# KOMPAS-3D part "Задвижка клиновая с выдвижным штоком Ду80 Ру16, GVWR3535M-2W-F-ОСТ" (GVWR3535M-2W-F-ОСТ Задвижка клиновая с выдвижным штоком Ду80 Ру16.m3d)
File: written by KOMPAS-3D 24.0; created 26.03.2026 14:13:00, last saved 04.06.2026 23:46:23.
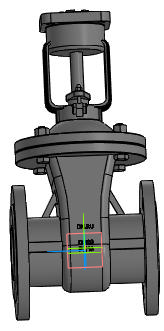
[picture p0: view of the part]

Document properties: Автор: R2D2; Полное имя файла: E:\Работа\Зайцев\GVWR3535M-2W-F-ОСТ Задвижка клиновая 30нж941нж DN.ru Ду50-200 Ру16\исходные данные\DN80\dn80\GVWR3535M-2W-F-ОСТ Задвижка клиновая с выдвижным штоком Ду80 Ру16.m3d

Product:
- Part/product: Задвижка клиновая с выдвижным штоком Ду80 Ру16  | designation GVWR3535M-2W-F-ОСТ
    Масса: 20.5
    Раздел спецификации: Прочие изделия
    Примечание: D040-09830

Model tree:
1. Операция без истории:1

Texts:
  GVWR3535M-2W-F-ОСТ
